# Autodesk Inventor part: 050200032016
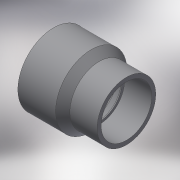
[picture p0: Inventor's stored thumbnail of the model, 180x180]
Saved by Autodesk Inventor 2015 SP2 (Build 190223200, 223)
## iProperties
Created: 2017-10
Part Number: 050200032016
Material: Generic
Description: PLASSON REDUCING SOCKET M.F.32(25)16 CEMENTED
Document SubType Name: Modeling
Designer: KIM
Density: 1 g/cm^3
Appearance: Default
Author: KIM
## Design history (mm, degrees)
derived "050200.ipt"
feature "Solid1::050200.ipt"
tag "TaggingFeature1"
body "Solid1"
other parameters: "d0" = 41, "d1" = 22, "d2" = 14, "d3" = 19, "d4" = 16, "d5" = 22, "d6" = 25, "d7" = 32, "d8" = 14.4, "d9" = 45 deg, "d12" = 0.25, "d_" = 25, "d_1" = 16, "L_" = 22, "l_" = 19, "l_1" = 14, "E_" = 22, "H_" = 41, "D_" = 32, "d11" = 45 deg
